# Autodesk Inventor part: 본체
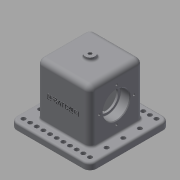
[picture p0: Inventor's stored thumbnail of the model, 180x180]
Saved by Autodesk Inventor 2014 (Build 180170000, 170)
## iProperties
Created: 2018-11
Part Number: 본체
Material: Generic
Document SubType Name: Modeling
Designer: kh
Density: 1 g/cm^3
Appearance: Default
Author: kh
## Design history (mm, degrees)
sketch "스케치1"
  geometry: L1 (-60, -60)-(60, -60); L2 (60, -60)-(60, 60); L3 (60, 60)-(-60, 60); L4 (-60, 60)-(-60, -60); L5 (-60, -60)-(60, 60); L6 (60, -60)-(-60, 60); 1 further point
  constraints: 12 end point, 2 midpoint, 2 parallel, 1 horizontal, 1 perpendicular
  dimensions: "d0" = 120 distance of L2.end L3.end; "d1" = 120 distance of L1.end L2.end
extrude "돌출1" new body sketch "스케치1" distance "d2" = 10; taper "d3" = 0 deg
sketch "스케치2"
  geometry: L1 (-40, -40)-(40, -40); L2 (40, -40)-(40, 40); L3 (40, 40)-(-40, 40); L4 (-40, 40)-(-40, -40); L5 (-40, -40)-(40, 40); L6 (40, -40)-(-40, 40); 1 further point
  constraints: 12 end point, 2 midpoint, 2 parallel, 1 horizontal, 1 perpendicular
  dimensions: "d4" = 80 distance of L2.end L3.end; "d5" = 80 distance of L1.end L2.end
extrude "돌출2" join sketch "스케치2" distance "d6" = 80; taper "d7" = 0 deg
sketch "스케치3"
  geometry: C1 r 7.5 at (0, 0); 1 further point
  constraints: 1 centre point, 1 coincident
  dimensions: "d8" = 15 diameter of C1
extrude "돌출3" join sketch "스케치3" distance "d9" = 5; taper "d10" = 0 deg
sketch "스케치4"
  geometry: L1 (40, 10)-(-40, 10) reference; L2 (40, 10)-(40, 90) reference; L3 (-40, 90)-(40, 90) reference; L4 (-40, 10)-(-40, 90) reference; L5 (-60, 0)-(60, 0) reference; L6 (60, 0)-(60, 10) reference; L7 (-60, 10)-(60, 10) reference; L8 (-60, 0)-(-60, 10) reference; L9 (7.5, 95)-(-7.5, 95) reference; L10 (-7.5, 90)-(7.5, 90) reference; L11 (0, 0)-(0, 48); L12 (0, 48)-(-40, 48); L13 (0, 48)-(40, 48); L14 (40, 48)-(26, 48); L15 (26, 48)-(26, 68); L16 (26, 68)-(40, 68); L17 (40, 68)-(40, 48); L18 (-40, 48)-(-26, 48); L19 (-26, 48)-(-26, 68); L20 (-26, 68)-(-40, 68); L21 (-40, 68)-(-40, 48); L22 (26, 48)-(-26, 48); L23 (-26, 48)-(-26, 64.5); L24 (26, 64.5)-(26, 48); L25 (26, 48)-(23, 48); L26 (23, 48)-(23, 64.5); L27 (23, 64.5)-(26, 64.5); L28 (26, 64.5)-(26, 48); L29 (-26, 48)-(-23, 48); L30 (-23, 48)-(-23, 64.5); L31 (-23, 64.5)-(-26, 64.5); L32 (-26, 64.5)-(-26, 48)
  constraints: 44 end point, 10 equal length, 7 perpendicular, 5 horizontal, 3 point on line
  dimensions: "d11" = 48 distance of L11.start L11.end; "d12" = 40 diameter of L16 L13; "d14" = 40 diameter of L20 L12; "d15" = 14 distance of L15.end L16.end; "d16" = 14 distance of L19.end L20.end; "d17" = 3 distance of L26.end L27.end; "d18" = 3 distance of L30.end L31.end; "d19" = 33 diameter of L31 L22; "d20" = 33 diameter of L27 L13
revolve "회전1" sketch "스케치4" stored, may be unused: angle "d21" = 90 deg
sketch "스케치5"
  geometry: L1 (-23, -30)-(23, -30); L2 (23, -30)-(23, 30); L3 (23, 30)-(-23, 30); L4 (-23, 30)-(-23, -30); L5 (-23, -30)-(23, 30); L6 (23, -30)-(-23, 30); 1 further point
  constraints: 12 end point, 2 midpoint, 2 parallel, 1 horizontal, 1 perpendicular
  dimensions: "d22" = 46 distance of L2.end L3.end; "d23" = 60 distance of L1.end L2.end
extrude "돌출4" cut sketch "스케치5" distance "d24" = 80; taper "d25" = 0 deg
sketch "스케치6" dims "d26" = 52
  geometry: L1 (0, 0)-(0, 80) reference; L2 (0, 0)-(80, 0) reference; L3 (80, 80)-(80, 0) reference; L4 (0, 80)-(80, 80) reference; L5 (38, 40)-(64, 40); C1 r 20 at (38, 40) reference; 2 further points
  constraints: 2 coincident, 2 end point, 1 horizontal alignment, 1 parallel, 2 other
hole "구멍1" sketch "스케치6" at (64, 40) diameter "d27" = 3.242; stored, may be unused: countersink angle "d31" = 90 deg, drill point angle "d33" = 118 deg; dims "d28" = 8, "d29" = 4, "d30" = 2, "d32" = 10
sketch "스케치7" dims "d34" = 52
  geometry: L1 (0, 80)-(0, 0) reference; L2 (0, 80)-(-80, 80) reference; L3 (-80, 0)-(-80, 80) reference; L4 (0, 0)-(-80, 0) reference; L5 (-38, 40)-(-64, 40); C1 r 20 at (-38, 40) reference; 2 further points
  constraints: 2 coincident, 2 end point, 1 horizontal alignment, 1 parallel, 2 other
hole "구멍2" sketch "스케치7" at (-64, 40) diameter "d35" = 3.242; stored, may be unused: countersink angle "d39" = 90 deg, drill point angle "d41" = 118 deg; dims "d36" = 8, "d37" = 4, "d38" = 2, "d40" = 10
sketch "스케치8"
  geometry: L1 (40, -10)-(40, 38); L2 (15.122, 41.675)-(64.897, 41.675); L3 (64.897, 41.675)-(64.897, 34.47); L4 (64.897, 34.47)-(15.122, 34.47); L5 (15.122, 34.47)-(15.122, 41.675)
  constraints: 2 end point, 1 vertical, 2 other
  dimensions: "d45" = 48 distance of L1.start L1.end
feature "엠보싱1" sketch "스케치8" dims "d0" = 120, "d1" = 120, "d46" = 0.5, "d47" = 0
sketch "스케치9"
  geometry: L1 (-50, -50)-(50, -50); L2 (50, -50)-(50, 50); L3 (50, 50)-(-50, 50); L4 (-50, 50)-(-50, -50); L5 (-50, -50)-(50, 50); L6 (50, -50)-(-50, 50); 3 further points
  constraints: 12 end point, 2 coincident, 2 midpoint, 2 parallel, 1 horizontal, 1 perpendicular
  dimensions: "d48" = 100 distance of L2.end L3.end; "d49" = 100 distance of L3.end L1.start
hole "구멍3" sketch "스케치9" at (-50, 50), (-50, -50) diameter "d50" = 6.6; stored, may be unused: countersink angle "d54" = 90 deg, drill point angle "d56" = 118 deg; dims "d51" = 6.6, "d52" = 4, "d53" = 2, "d55" = 10
sketch "스케치10"
  geometry: L1 (-50, -25)-(50, -25); L2 (50, -25)-(50, 25); L3 (50, 25)-(-50, 25); L4 (-50, 25)-(-50, -25); L5 (-50, -25)-(50, 25); L6 (50, -25)-(-50, 25); 7 further points
  constraints: 12 end point, 4 coincident, 4 midpoint, 2 parallel, 1 horizontal, 1 perpendicular
  dimensions: "d60" = 50 distance of L3.end L1.start; "d61" = 100 distance of L2.end L3.end
hole "구멍4" sketch "스케치10" at (-50, 25), (-50, 0), (-50, -25), (50, 25), (50, 0), (50, -25) diameter "d62" = 6.6; stored, may be unused: countersink angle "d66" = 90 deg, drill point angle "d68" = 118 deg; dims "d63" = 6.6, "d64" = 4, "d65" = 2, "d67" = 10
fillet "모깎기1" dims "d69" = 10, "d70" = 8
fillet "모깎기2" dims "d71" = 8, "d72" = 3
hole "구멍5" diameter "d75" = 4.917; stored, may be unused: countersink angle "d79" = 90 deg, drill point angle "d81" = 118 deg; dims "d73" = 10, "d74" = 10, "d76" = 6.6, "d77" = 4, "d78" = 2, "d80" = 10
fillet "모깎기3" dims "d82" = 0.6
chamfer "모따기1" distance "d83" = 1; stored, may be unused: second distance "d84" = 2, angle "d85" = 45 deg
fillet "모깎기4" dims "d86" = 3
fillet "모깎기5" dims "d87" = 3
node "솔리드1"
pattern_circular "원형 패턴1" dims angle "d43" = 360 deg
pattern_linear "직사각형 패턴1" dims "d59" = 10
node "투영된 루프1"
node "투영된 루프2"
node "투영된 루프3"
node "투영된 루프4"
node "투영된 루프5"
